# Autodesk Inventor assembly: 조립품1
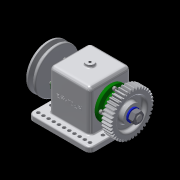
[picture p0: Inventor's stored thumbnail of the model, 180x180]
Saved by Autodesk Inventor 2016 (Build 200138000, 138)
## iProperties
Created: 2018-11
Part Number: 조립품1
Document SubType Name: Assembly
Designer: PC-18
Author: PC-18
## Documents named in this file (13)
- C:\Users\PC-18\Desktop\481108V1015\조립품1.iam
- C:\Users\PC-18\Desktop\481108V1015\본체.ipt
- C:\Users\PC-18\Desktop\481108V1015\베어링 6203.ipt
- C:\Users\PC-18\Desktop\481108V1015\커버.ipt
- C:\Users\PC-18\Desktop\481108V1015\오일 실 26 38 8.ipt
- C:\Users\PC-18\Desktop\481108V1015\축.ipt
- C:\Users\PC-18\Desktop\481108V1015\부시.ipt
- C:\Users\PC-18\Desktop\481108V1015\키 5x5x12.ipt
- C:\Users\PC-18\Desktop\481108V1015\V벨트풀리.ipt
- C:\Users\PC-18\Desktop\481108V1015\스퍼기어.ipt
- C:\Users\PC-18\Desktop\481108V1015\와셔 12x24.ipt
- C:\Users\PC-18\Desktop\481108V1015\너트 M12x1.25.ipt
- C:\Users\PC-18\Desktop\481108V1015\볼트 M4.ipt
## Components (1 placed, 1 different names)
1. V벨트풀리:1
